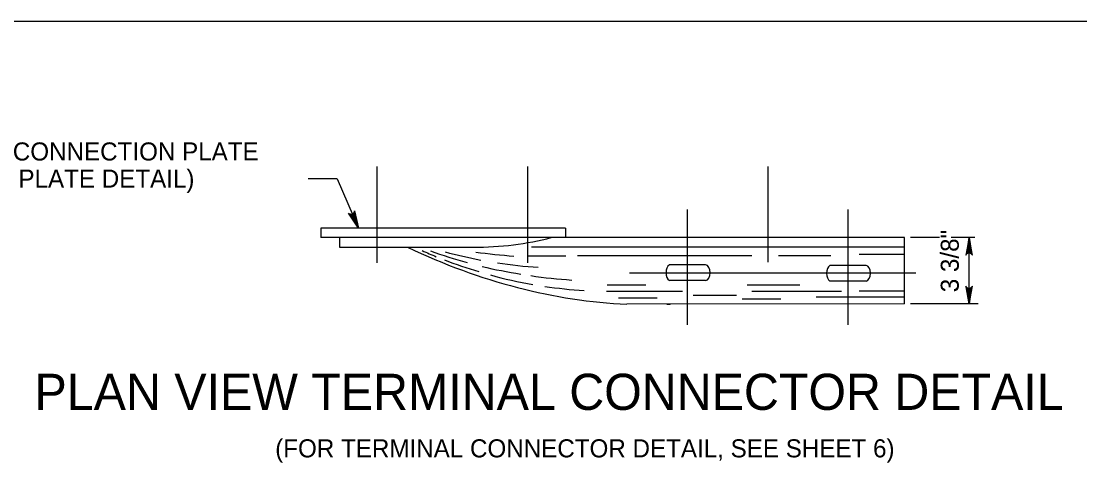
# Model space of a CAD drawing. Extents: x 632007860 to 635435983, y 295418622 to 297794622.
# Drawn here: x 634661713 to 634840166, y 297111180 to 297185622 of the extents above; entities that cross this region are included whole.
import ezdxf

# ---------------------------------------------------------------- set-up
doc = ezdxf.new("R2010")
doc.units = 0
for name, color, linetype in [('1', 7, 'Continuous'), ('8', 7, 'Continuous'), ('S-DETL-DIMS', 7, 'Continuous'), ('S-DETL-T120', 7, 'Continuous'), ('S-DETL-T240', 7, 'Continuous'), ('S-STEL', 7, 'Continuous')]:
    doc.layers.add(name, color=color, linetype=linetype)

msp = doc.modelspace()

# ---------------------------------------------------------------- linework, layer by layer
at = {"layer": '1'}
msp.add_line((634570860, 297185622), (635356860, 297185622), dxfattribs=at)
at = {"layer": '8'}
for p, q in [((634721712, 297144870), (634721712, 297161144)), ((634747129, 297144870), (634747129, 297161144)), ((634787606, 297145011), (634787606, 297161144)), ((634774048, 297134431), (634774048, 297153889)), ((634801100, 297134438), (634801100, 297153889)), ((634812529, 297143161), (634764250, 297143154))]:
    msp.add_line(p, q, dxfattribs=at)
at = {"layer": 'S-DETL-DIMS'}
for p, q in [((634714986, 297159031), (634710110, 297159031)), ((634714986, 297159031), (634718588, 297150741)), ((634816499, 297149159), (634811623, 297149159)), ((634822464, 297149159), (634818499, 297149159)), ((634821499, 297137989), (634821499, 297149159)), ((634823021, 297137989), (634811623, 297137989))]:
    msp.add_line(p, q, dxfattribs=at)
for points in [[(634718588, 297150741), (634716899, 297153234), (634717017, 297153161), (634717135, 297153088), (634717249, 297153074), (634717364, 297153059), (634717462, 297153083), (634717559, 297153107), (634717644, 297153162), (634717728, 297153218), (634717795, 297153311), (634717863, 297153404), (634717890, 297153541), (634717917, 297153677), (634718588, 297150741), (634717890, 297153541), (634717863, 297153404), (634718588, 297150741), (634717795, 297153311), (634717728, 297153218), (634718588, 297150741), (634717644, 297153162), (634717559, 297153107), (634718588, 297150741), (634717462, 297153083), (634717364, 297153059), (634718588, 297150741), (634717249, 297153074), (634717135, 297153088), (634718588, 297150741), (634717017, 297153161)], [(634821499, 297149159), (634820944, 297146200), (634821023, 297146314), (634821102, 297146428), (634821201, 297146487), (634821300, 297146545), (634821400, 297146562), (634821499, 297146579), (634821598, 297146562), (634821697, 297146545), (634821796, 297146487), (634821896, 297146428), (634821975, 297146314), (634822054, 297146200), (634821499, 297149159), (634821975, 297146314), (634821896, 297146428), (634821499, 297149159), (634821796, 297146487), (634821697, 297146545), (634821499, 297149159), (634821598, 297146562), (634821499, 297146579), (634821499, 297149159), (634821400, 297146562), (634821300, 297146545), (634821499, 297149159), (634821201, 297146487), (634821102, 297146428), (634821499, 297149159), (634821023, 297146314)], [(634821499, 297137989), (634822054, 297140948), (634821975, 297140834), (634821896, 297140720), (634821796, 297140661), (634821697, 297140602), (634821598, 297140585), (634821499, 297140568), (634821400, 297140585), (634821300, 297140602), (634821201, 297140661), (634821102, 297140720), (634821023, 297140834), (634820944, 297140948), (634821499, 297137989), (634821023, 297140834), (634821102, 297140720), (634821499, 297137989), (634821201, 297140661), (634821300, 297140602), (634821499, 297137989), (634821400, 297140585), (634821499, 297140568), (634821499, 297137989), (634821598, 297140585), (634821697, 297140602), (634821499, 297137989), (634821796, 297140661), (634821896, 297140720), (634821499, 297137989), (634821975, 297140834)]]:
    msp.add_lwpolyline(points, dxfattribs=at)
at = {"layer": 'S-STEL'}
for p, q in [((634753475, 297150744), (634712200, 297150741)), ((634712200, 297150741), (634712200, 297149152)), ((634810625, 297149159), (634712200, 297149152)), ((634753475, 297150741), (634753475, 297149096)), ((634810625, 297137984), (634810625, 297149159)), ((634751055, 297149152), (634715375, 297149152)), ((634715375, 297149152), (634715375, 297147507)), ((634715375, 297147507), (634727022, 297147507)), ((634726658, 297147507), (634737896, 297147507)), ((634810625, 297147514), (634747764, 297147507)), ((634753519, 297146021), (634747003, 297146021)), ((634784879, 297146052), (634755470, 297146045)), ((634798208, 297146052), (634789361, 297146052)), ((634810625, 297146280), (634802963, 297146280)), ((634777071, 297144550), (634770975, 297144550)), ((634804122, 297144463), (634798026, 297144463)), ((634767009, 297141138), (634760493, 297141138)), ((634777071, 297141902), (634770975, 297141902)), ((634776563, 297141902), (634771483, 297141902)), ((634792946, 297141145), (634784100, 297141145)), ((634804122, 297141814), (634798026, 297141814)), ((634803614, 297141814), (634798534, 297141814)), ((634773183, 297140050), (634760374, 297140050)), ((634768898, 297138921), (634762381, 297138921)), ((634782310, 297139396), (634774969, 297139390)), ((634789756, 297138740), (634783240, 297138740)), ((634800018, 297140056), (634784879, 297140056)), ((634810625, 297139088), (634795712, 297139088)), ((634810625, 297140116), (634802984, 297140116)), ((634810625, 297137984), (634763818, 297137920))]:
    msp.add_line(p, q, dxfattribs=at)
for centre, start, end in [((634761661, 297219517), 245.9713, 247.84038), ((634757983, 297221539), 249.92293, 254.60468), ((634753938, 297223440), 254.86039, 259.30149), ((634749831, 297225340), 261.6849, 266.35001), ((634761661, 297219517), 248.90002, 253.30435), ((634757983, 297221539), 256.49028, 261.27182), ((634753938, 297223440), 261.3526, 266.35001), ((634761661, 297219517), 254.79056, 260.08274), ((634759577, 297221294), 261.3526, 266.35001), ((634761661, 297219517), 261.53517, 266.35001), ((634767193, 297217310), 272.41176, 272.90741)]:
    msp.add_arc(centre, 79461, start, end, dxfattribs=at)
for centre, major_axis, ratio, start_param, end_param in [((634744016, 297217310), (67875, -61215), 0.7464226, 5.0936318, 5.5493346), ((634737848, 297160658), (27269, 0), 0.4822531, 4.7141547, 5.2179741), ((634771342, 297143226), (0, 1443), 0.64, 0.4090626, 2.73253), ((634776996, 297143226), (0, 1329), 0.64, 3.2290764, 6.1957016), ((634798393, 297143138), (0, 1443), 0.64, 0.4090626, 2.73253), ((634804048, 297143138), (0, 1329), 0.64, 3.2290764, 6.1957016)]:
    msp.add_ellipse(centre, major_axis=major_axis, ratio=ratio, start_param=start_param, end_param=end_param, dxfattribs=at)

# ---------------------------------------------------------------- texts
at = {"layer": 'S-DETL-T120'}
for s, p in [('CONNECTION PLATE', (634660304, 297162139)), ('(SEE CONNECTION PLATE DETAIL)', (634622072, 297157567)), ('(FOR TERMINAL CONNECTOR DETAIL, SEE SHEET 6)', (634704534, 297112097))]:
    msp.add_text(s, height=3048.01, dxfattribs=at).set_placement(p)
msp.add_text('3 3/8"', height=3048, rotation=90, dxfattribs=at).set_placement((634819769, 297139935))
at = {"layer": 'S-DETL-T240'}
msp.add_text('PLAN VIEW TERMINAL CONNECTOR DETAIL', height=6096, dxfattribs=at).set_placement((634663965, 297120099))

doc.saveas('drawing.dxf')
